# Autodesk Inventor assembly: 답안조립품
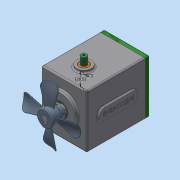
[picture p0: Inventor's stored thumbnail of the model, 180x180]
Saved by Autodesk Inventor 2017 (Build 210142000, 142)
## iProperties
Part Number: 답안조립품
Material: 일반
Document SubType Name: Assembly
Designer: MRC
Mass: 2669.46 g
Surface Area: 1952.92 cm^2
Volume: 798.897 cm^3
Density: 3.34143 g/cm^3
Author: MRC
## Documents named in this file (17)
- C:\Users\MRC\Desktop\새 폴더 (2)\610205V1001\답안조립품.iam
- C:\Users\MRC\Desktop\새 폴더 (2)\610205V1001\본체.ipt
- C:\Users\MRC\Desktop\새 폴더 (2)\610205V1001\가변스프링.ipt
- C:\Users\MRC\Desktop\새 폴더 (2)\610205V1001\멈춤나사 M3x8.ipt
- C:\Users\MRC\Desktop\새 폴더 (2)\610205V1001\메인 기어 축.ipt
- C:\Users\MRC\Desktop\새 폴더 (2)\610205V1001\베어링 608.ipt
- C:\Users\MRC\Desktop\새 폴더 (2)\610205V1001\베어링 6903.ipt
- C:\Users\MRC\Desktop\새 폴더 (2)\610205V1001\볼트 M4 x 10.ipt
- C:\Users\MRC\Desktop\새 폴더 (2)\610205V1001\부시.ipt
- C:\Users\MRC\Desktop\새 폴더 (2)\610205V1001\서브 기어 축.ipt
- C:\Users\MRC\Desktop\새 폴더 (2)\610205V1001\슬라이더.ipt
- C:\Users\MRC\Desktop\새 폴더 (2)\610205V1001\오일 실 8 22 7.ipt
- C:\Users\MRC\Desktop\새 폴더 (2)\610205V1001\오일 실 17 30 8.ipt
- C:\Users\MRC\Desktop\새 폴더 (2)\610205V1001\커버.ipt
- C:\Users\MRC\Desktop\새 폴더 (2)\610205V1001\키 5 x 5 x 24.ipt
- C:\Users\MRC\Desktop\새 폴더 (2)\610205V1001\팬날개.ipt
- 팬날개.ipt
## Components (1 placed, 1 different names)
1. 가변스프링:1
